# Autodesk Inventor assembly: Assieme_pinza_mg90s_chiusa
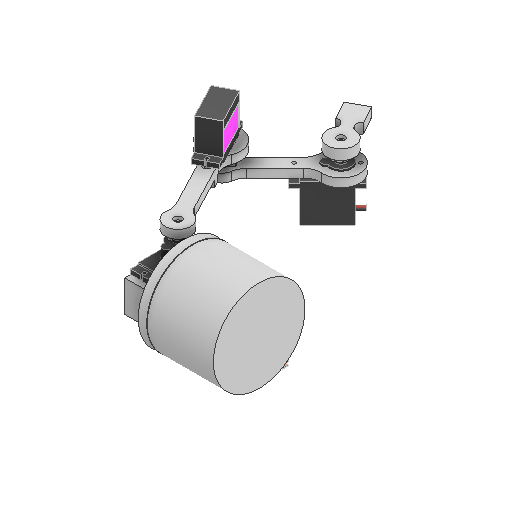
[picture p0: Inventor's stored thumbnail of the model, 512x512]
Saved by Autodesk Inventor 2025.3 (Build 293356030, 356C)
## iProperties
Created: 2026-03
Part Number: Assieme_pinza_mg90s_chiusa
Document SubType Name: Assembly
Designer: Ryzen5700u
Sending System: Autodesk Inventor 2025
Preprocessor: ST-DEVELOPER v20
Title: Assieme_pinza_mg90s_chiusa.stp
Author: R5800u
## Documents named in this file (9)
- C:\Users\R5800u\Desktop\robot eco\Assieme_pinza_mg90s_chiusa\Assieme_pinza_mg90s_chiusa.iam
- C:\Users\R5800u\Desktop\robot eco\Assieme_pinza_mg90s_chiusa\MG90_ldb.ipt
- C:\Users\R5800u\Desktop\robot eco\Assieme_pinza_mg90s_chiusa\MG90S ARM 2x.ipt
- C:\Users\R5800u\Desktop\robot eco\braccio_1.ipt
- C:\Users\R5800u\Desktop\robot eco\braccio_3.ipt
- C:\Users\R5800u\Desktop\robot eco\braccio_2.ipt
- C:\Users\R5800u\Desktop\robot eco\base.ipt
- C:\Users\R5800u\Desktop\robot eco\base_cilindro.ipt
- C:\Users\R5800u\Desktop\robot eco\MG90_ldb_v2.ipt
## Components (14 placed, 8 different names)
1. MG90_ldb:1 — Rotazionale:1, Coincidente:1, Allineato:1
2. MG90S ARM 2x:1 — Rotazionale:1, Coincidente:2, Angolo:2
3. braccio_1:1 — Coincidente:1, Coincidente:2, Coincidente:3, Angolo:1, Coincidente:4, Angolo:2
4. MG90_ldb:2 — Coincidente:3, Angolo:1, Coincidente:4, Rotazionale:2, Coincidente:11
5. MG90S ARM 2x:2 — Rotazionale:2, Coincidente:12, Angolo:8
6. MG90_ldb:3 — Rotazionale:4, Coincidente:7, Coincidente:13, Coincidente:14, Angolo:9
7. braccio_3:1 — Coincidente:7, Coincidente:8, Angolo:7
8. MG90S ARM 2x:3 — Rotazionale:4, Coincidente:8, Angolo:7
9. base:1 — Allineato:1, Coincidente:9, Coincidente:10, Coincidente:15, Angolo:10
10. MG90_ldb:4 — Rotazionale:5, Coincidente:10, Angolo:5, Coincidente:17, Angolo:10, Coincidente:18
11. MG90S ARM 2x:4 — Rotazionale:5, Coincidente:9, Angolo:5
12. base_cilindro:1 — Coincidente:15, Coincidente:17, Coincidente:18, Allineato:3
13. braccio_2:1 — Coincidente:11, Coincidente:12, Angolo:8, Coincidente:13, Coincidente:14, Angolo:9
14. MG90_ldb_v2:1
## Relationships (28: Mate 15, Angle 7, RevoluteJoint 4, Flush 2)
- Rotazionale:1 [RevoluteJoint]: MG90_ldb:1 ↔ MG90S ARM 2x:1
- Coincidente:1 [Mate]: MG90_ldb:1 ↔ braccio_1:1
- Coincidente:2 [Mate]: MG90S ARM 2x:1 ↔ braccio_1:1
- Coincidente:3 [Mate]: braccio_1:1 ↔ MG90_ldb:2
- Angolo:1 [Angle]: braccio_1:1 ↔ MG90_ldb:2
- Coincidente:4 [Mate]: braccio_1:1 ↔ MG90_ldb:2
- Angolo:2 [Angle]: MG90S ARM 2x:1 ↔ braccio_1:1
- Rotazionale:2 [RevoluteJoint]: MG90_ldb:2 ↔ MG90S ARM 2x:2
- Rotazionale:4 [RevoluteJoint]: MG90_ldb:3 ↔ MG90S ARM 2x:3
- Coincidente:7 [Mate]: MG90_ldb:3 ↔ braccio_3:1
- Coincidente:8 [Mate]: braccio_3:1 ↔ MG90S ARM 2x:3
- Allineato:1 [Flush]: MG90_ldb:1 ↔ base:1
- Rotazionale:5 [RevoluteJoint]: MG90_ldb:4 ↔ MG90S ARM 2x:4
- Coincidente:9 [Mate]: base:1 ↔ MG90S ARM 2x:4
- Coincidente:10 [Mate]: base:1 ↔ MG90_ldb:4
- Angolo:5 [Angle]: MG90_ldb:4 ↔ MG90S ARM 2x:4
- Angolo:7 [Angle]: braccio_3:1 ↔ MG90S ARM 2x:3
- Coincidente:11 [Mate]: MG90_ldb:2 ↔ braccio_2:1
- Coincidente:12 [Mate]: MG90S ARM 2x:2 ↔ braccio_2:1
- Angolo:8 [Angle]: MG90S ARM 2x:2 ↔ braccio_2:1
- Coincidente:13 [Mate]: MG90_ldb:3 ↔ braccio_2:1
- Coincidente:14 [Mate]: MG90_ldb:3 ↔ braccio_2:1
- Angolo:9 [Angle]: MG90_ldb:3 ↔ braccio_2:1
- Coincidente:15 [Mate]: base:1 ↔ base_cilindro:1
- Coincidente:17 [Mate]: MG90_ldb:4 ↔ base_cilindro:1
- Angolo:10 [Angle]: base:1 ↔ MG90_ldb:4
- Coincidente:18 [Mate]: MG90_ldb:4 ↔ base_cilindro:1
- Allineato:3 [Flush]: base_cilindro:1
